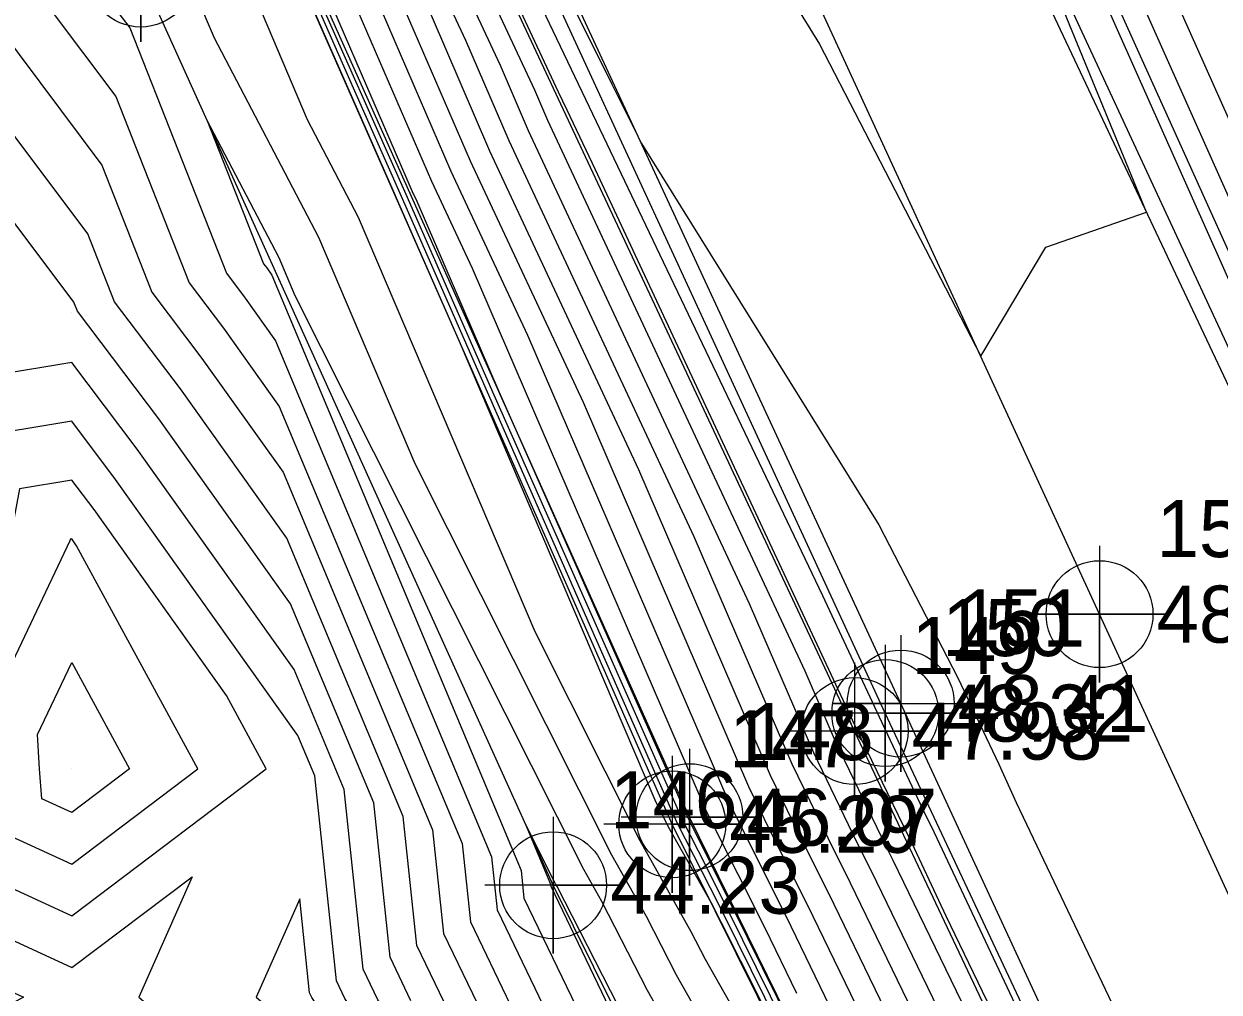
# Model space of a CAD drawing. Extents: x 2090860 to 2091277, y 159470 to 160080.
# Drawn here: x 2091087.9 to 2091140.3, y 159590.2 to 159632.7 of the extents above; entities that cross this region are included whole.
import ezdxf

# ---------------------------------------------------------------- set-up
doc = ezdxf.new("R2010")
doc.units = 0
for name, color, linetype in [('DTM Contours Major', 7, 'Continuous'), ('DTM Contours Minor', 7, 'Continuous'), ('Exist DTM Breakline', 7, 'Continuous'), ('Exist DTM Breakline Cogo Elevation', 7, 'Continuous'), ('Exist DTM Breakline Cogo Number', 7, 'Continuous'), ('Exist DTM Breakline Cogo Point CELL', 7, 'Continuous'), ('Exist DTM Crownline', 7, 'Continuous'), ('Exist DTM Crownline Cogo Elevation', 7, 'Continuous'), ('Exist DTM Crownline Cogo Number', 7, 'Continuous'), ('Exist DTM Crownline Cogo Point CELL', 7, 'Continuous'), ('Exist DTM QL2 LIDAR Elevation Point', 7, 'Continuous'), ('Exist Roads EOP', 7, 'Continuous'), ('Exist Roads EOP Cogo Elevation', 7, 'Continuous'), ('Exist Roads EOP Cogo Number', 7, 'Continuous'), ('Exist Roads EOP Cogo Point CELL', 7, 'Continuous'), ('Exist Roads EOT', 7, 'Continuous'), ('Exist Roads EOT Cogo Elevation', 7, 'Continuous'), ('Exist Roads EOT Cogo Number', 7, 'Continuous'), ('Exist Roads EOT Cogo Point CELL', 7, 'Continuous')]:
    doc.layers.add(name, color=color, linetype=linetype)

msp = doc.modelspace()

# ---------------------------------------------------------------- linework, layer by layer
at = {"layer": 'DTM Contours Major'}
for points in [[(2091079.813, 159694.479), (2091091.479, 159670.351), (2091092.674, 159667.942), (2091092.718, 159667.852), (2091101.365, 159650.434), (2091105.185, 159642.793), (2091106.067, 159640.964), (2091111.338, 159629.685), (2091111.718, 159628.889), (2091112.961, 159626.284), (2091124.433, 159601.716), (2091124.607, 159601.347), (2091126.942, 159596.528), (2091128.343, 159593.558), (2091139.93, 159569.539)], [(2091077.176, 159683.472), (2091085.357, 159667.475), (2091085.495, 159667.182), (2091086.555, 159664.923), (2091087.913, 159662.036), (2091093.577, 159649.962), (2091099.498, 159637.849), (2091099.709, 159637.399), (2091104.938, 159625.32), (2091105.136, 159624.896), (2091108.736, 159616.547), (2091117.028, 159597.858), (2091117.244, 159597.435), (2091119.625, 159592.62), (2091130.861, 159569.9)], [(2091082.79, 159680.214), (2091088.287, 159668.846), (2091088.85, 159667.711), (2091089.525, 159666.328), (2091095.999, 159653.287), (2091102.781, 159639.414), (2091105.76, 159633.037), (2091108.329, 159627.103), (2091114.857, 159613.131), (2091120.634, 159599.73), (2091121.876, 159597.167), (2091123.209, 159594.519), (2091129.912, 159580.676)], [(2091163.429, 159579.673), (2091153.599, 159600.613), (2091150.617, 159606.792), (2091148.169, 159612.011), (2091147.459, 159613.481), (2091138.047, 159634.57), (2091135.191, 159640.875), (2091131.528, 159649.079), (2091130.314, 159651.757), (2091121.742, 159670.624), (2091117.989, 159679.115)], [(2091129.857, 159570.34), (2091117.802, 159591.64), (2091117.171, 159592.866), (2091114.927, 159596.852), (2091110.323, 159606.006), (2091102.573, 159624.179), (2091100.334, 159628.452), (2091096.842, 159636.697), (2091095.262, 159642.075), (2091085.023, 159664.299)], [(2091080.029, 159649.409), (2091088.053, 159636.828), (2091089.011, 159633.367), (2091091.931, 159629.479), (2091095.15, 159621.315), (2091096.661, 159619.317), (2091099.104, 159615.886), (2091107.122, 159596.733), (2091107.485, 159593.301), (2091109.226, 159589.679)], [(2091110.007, 159579.993), (2091110.002, 159580.004), (2091103.432, 159589.881), (2091102.785, 159591.228), (2091101.952, 159599.105), (2091099.755, 159604.353), (2091092.873, 159614.018), (2091090, 159617.816), (2091083.295, 159616.705), (2091082.036, 159610), (2091081.379, 159608.621), (2091081.89, 159600), (2091082.493, 159592.493), (2091087.89, 159590), (2091082.789, 159587.211), (2091083.053, 159580), (2091090, 159570.963), (2091096.054, 159573.946), (2091100, 159579.609), (2091100.406, 159579.594), (2091110, 159579.988), (2091110.007, 159579.993)], [(2091088.689, 159598.689), (2091088.584, 159600), (2091088.495, 159601.505), (2091090, 159604.666), (2091092.536, 159600), (2091090, 159598.084), (2091088.689, 159598.689)]]:
    msp.add_lwpolyline(points, dxfattribs=at)
at = {"layer": 'DTM Contours Minor'}
for points in [[(2091080.51, 159698.642), (2091091.966, 159674.206), (2091093.26, 159671.558), (2091094.64, 159668.709), (2091094.706, 159668.575), (2091095.273, 159667.441), (2091100.175, 159657.278), (2091105.245, 159647.055), (2091107.931, 159641.569), (2091110.32, 159636.766), (2091113.678, 159630.044), (2091114.986, 159627.423), (2091125.393, 159610.705), (2091128.86, 159603.992), (2091130.664, 159600.208), (2091131.424, 159598.524), (2091140.273, 159579.961)], [(2091080.273, 159695.626), (2091092.352, 159670.911), (2091092.91, 159669.758), (2091093.68, 159668.217), (2091100.229, 159655.117), (2091106.917, 159641.251), (2091109.366, 159636.01), (2091112.54, 159629.361), (2091122.928, 159607.603), (2091125.409, 159602.289), (2091127.327, 159598.223), (2091127.819, 159597.207), (2091138.555, 159574.438)], [(2091072.913, 159694.755), (2091083.535, 159676.648), (2091087.489, 159668.47), (2091087.894, 159667.653), (2091088.727, 159665.947), (2091093.416, 159656.501), (2091101.96, 159639.023), (2091104.247, 159634.128), (2091107.481, 159626.657), (2091112.427, 159616.072), (2091119.685, 159599.236), (2091120.595, 159597.359), (2091122.273, 159594.024), (2091127.204, 159583.841)], [(2091070.474, 159693.642), (2091081.681, 159673.757), (2091084.964, 159667.339), (2091085.735, 159665.698), (2091086.157, 159664.799), (2091094.809, 159646.403), (2091098.918, 159637.644), (2091102.338, 159629.862), (2091104.449, 159625.11), (2091112.732, 159606.254), (2091116.546, 159597.659), (2091118.37, 159594.073), (2091119.204, 159592.386), (2091123.926, 159582.838)], [(2091080.558, 159690.913), (2091090.681, 159669.974), (2091091.718, 159667.884), (2091091.92, 159667.471), (2091103.748, 159643.645), (2091105.242, 159640.588), (2091110.299, 159629.767), (2091110.873, 159628.44), (2091122.148, 159604.306), (2091123.481, 159601.214), (2091125.721, 159596.589), (2091126.015, 159596.005), (2091138.036, 159571.181)], [(2091073.926, 159690.732), (2091084.279, 159673.082), (2091086.691, 159668.093), (2091086.938, 159667.595), (2091087.929, 159665.566), (2091090.833, 159659.715), (2091101.14, 159638.632), (2091102.735, 159635.218), (2091106.633, 159626.212), (2091109.996, 159619.013), (2091118.736, 159598.741), (2091119.313, 159597.552), (2091121.338, 159593.528), (2091124.496, 159587.006)], [(2091074.923, 159688.329), (2091081.29, 159675.881), (2091085.023, 159669.516), (2091085.893, 159667.717), (2091085.982, 159667.538), (2091087.13, 159665.185), (2091088.251, 159662.929), (2091100.319, 159638.24), (2091101.222, 159636.308), (2091105.785, 159625.766), (2091107.566, 159621.955), (2091117.788, 159598.247), (2091118.031, 159597.744), (2091120.402, 159593.033), (2091121.788, 159590.171)], [(2091081.302, 159687.347), (2091089.883, 159669.598), (2091090.762, 159667.827), (2091091.122, 159667.09), (2091101.165, 159646.859), (2091104.422, 159640.197), (2091108.786, 159630.857), (2091110.025, 159627.994), (2091119.717, 159607.248), (2091122.532, 159600.719), (2091124.44, 159596.782), (2091125.08, 159595.509), (2091135.328, 159574.346)], [(2091092.675, 159687.628), (2091098.961, 159674.873), (2091100.257, 159672.453), (2091101.069, 159671.14), (2091105.715, 159663.627), (2091115.58, 159644.724), (2091116.703, 159642.969), (2091121.642, 159633.637), (2091122.802, 159631.775), (2091129.869, 159618.089), (2091132.718, 159622.878), (2091137.14, 159624.41), (2091135.353, 159628.744), (2091131.259, 159638.725), (2091131.05, 159639.235), (2091130.694, 159640.103), (2091126.571, 159649.248), (2091126.304, 159649.847), (2091125.204, 159652.293), (2091113.546, 159676.999), (2091113.443, 159677.236), (2091111.307, 159681.76)], [(2091082.046, 159683.781), (2091089.085, 159669.222), (2091089.806, 159667.769), (2091090.323, 159666.709), (2091098.582, 159650.073), (2091103.601, 159639.806), (2091107.273, 159631.947), (2091109.177, 159627.548), (2091117.287, 159610.189), (2091121.583, 159600.225), (2091123.158, 159596.974), (2091124.144, 159595.014), (2091132.62, 159577.511)], [(2091160.862, 159578.349), (2091151.097, 159599.184), (2091148.077, 159605.5), (2091147.174, 159607.39), (2091144.949, 159612.13), (2091141.732, 159619.248), (2091132.693, 159639.533), (2091131.752, 159641.619), (2091127.777, 159650.544), (2091122.382, 159662.543), (2091115.863, 159676.89), (2091115.422, 159677.888), (2091115.345, 159678.061), (2091113.296, 159682.58)], [(2091106.329, 159589.78), (2091105.135, 159592.265), (2091104.537, 159597.919), (2091099.429, 159610.12), (2091094.767, 159616.667), (2091091.883, 159620.481), (2091090.706, 159623.465), (2091084.527, 159631.691), (2091082.5, 159639.015), (2091080.009, 159642.921), (2091074.236, 159645.764), (2091070, 159645.752), (2091065.862, 159650), (2091067.247, 159652.753), (2091070, 159653.131), (2091071.999, 159660.381), (2091071.72, 159660.849), (2091070.48, 159669.697), (2091073.008, 159669.437), (2091070, 159676.646), (2091068.908, 159678.908)], [(2091079.429, 159678.614), (2091085.16, 159667.407), (2091085.615, 159666.44), (2091086.356, 159664.861), (2091091.361, 159654.219), (2091099.113, 159637.695), (2091100.516, 159634.501), (2091104.653, 159625.193), (2091108.518, 159616.394), (2091116.787, 159597.759), (2091117.807, 159595.754), (2091119.414, 159592.503), (2091128.512, 159574.108)], [(2091162.131, 159578.985), (2091150.559, 159603.635), (2091149.359, 159606.123), (2091146.488, 159612.24), (2091146.209, 159612.821), (2091135.187, 159637.514), (2091133.962, 159640.22), (2091129.606, 159649.977), (2091129.069, 159651.161), (2091118.802, 159673.757), (2091116.705, 159678.502)], [(2091132.489, 159565.487), (2091119.34, 159591.568), (2091118.994, 159592.269), (2091118.933, 159592.393), (2091118.041, 159594.145), (2091116.161, 159597.483), (2091115.582, 159598.635), (2091107.01, 159618.735), (2091104.245, 159625.028), (2091104.159, 159625.223), (2091098.723, 159637.593), (2091098.257, 159638.587), (2091085.958, 159664.737)], [(2091127.322, 159571.892), (2091116.525, 159590.966), (2091115.21, 159593.526), (2091113.692, 159596.22), (2091105.065, 159613.377), (2091100.835, 159623.295), (2091096.258, 159632.032), (2091094.714, 159635.676), (2091091.322, 159647.221), (2091083.738, 159663.682)], [(2091080.039, 159652.653), (2091090.83, 159635.734), (2091091.253, 159634.205), (2091092.544, 159632.486), (2091096.783, 159621.732), (2091097.608, 159620.641), (2091098.942, 159618.769), (2091108.415, 159596.14), (2091108.66, 159593.82), (2091110.674, 159589.629)], [(2091104.88, 159589.83), (2091103.96, 159591.747), (2091103.244, 159598.512), (2091099.592, 159607.237), (2091093.82, 159615.342), (2091090.249, 159620.064), (2091090.093, 159620.458), (2091082.284, 159630.854), (2091080, 159639.109), (2091070.926, 159639.074), (2091073.494, 159630), (2091070, 159622.762), (2091067.148, 159620), (2091070, 159615.229), (2091075.044, 159610), (2091070, 159603.341), (2091069.417, 159600.583), (2091067.816, 159600), (2091070, 159597.318), (2091074.705, 159600), (2091080, 159603.65), (2091080.216, 159600), (2091080.944, 159590.944), (2091082.987, 159590)], [(2091086.769, 159632.529), (2091091.319, 159626.472), (2091093.516, 159620.898), (2091095.714, 159617.992), (2091099.267, 159613.003), (2091105.83, 159597.326), (2091106.31, 159592.783), (2091107.777, 159589.73)], [(2091121.017, 159580.102), (2091115.248, 159590.293), (2091113.248, 159594.185), (2091112.457, 159595.589), (2091099.806, 159620.747), (2091099.097, 159622.411), (2091095.932, 159628.452), (2091098.417, 159622.149), (2091098.555, 159621.966), (2091098.779, 159621.652), (2091109.708, 159595.547), (2091109.835, 159594.338), (2091112.122, 159589.579)], [(2091101.984, 159589.931), (2091101.609, 159590.71), (2091100.659, 159599.698), (2091099.917, 159601.47), (2091091.925, 159612.693), (2091090, 159615.239), (2091085.506, 159614.494), (2091084.662, 159610), (2091083.158, 159606.842), (2091083.563, 159600), (2091084.042, 159594.042), (2091090, 159591.29), (2091095.276, 159595.276), (2091092.937, 159590), (2091100, 159583.938), (2091105.788, 159584.212), (2091101.984, 159589.931)], [(2091090.978, 159611.368), (2091090, 159612.662), (2091087.717, 159612.283), (2091087.288, 159610), (2091084.937, 159605.063), (2091085.237, 159600), (2091085.591, 159595.591), (2091090, 159593.555), (2091098.531, 159600), (2091096.782, 159603.218), (2091090.978, 159611.368)], [(2091090.031, 159610.043), (2091090, 159610.085), (2091089.927, 159610.073), (2091089.914, 159610), (2091086.716, 159603.284), (2091086.911, 159600), (2091087.14, 159597.14), (2091090, 159595.819), (2091095.534, 159600), (2091090.215, 159609.785), (2091090.031, 159610.043)], [(2091127.831, 159563.023), (2091114.712, 159588.312), (2091113.972, 159589.62), (2091111.287, 159594.844), (2091111.223, 159594.958), (2091109.886, 159597.615), (2091111, 159594.954), (2091111.011, 159594.856), (2091113.571, 159589.528), (2091113.706, 159589.325), (2091126.097, 159563.682), (2091125.546, 159563.322), (2091126.31, 159562.346), (2091130.432, 159555.15), (2091130.628, 159554.906), (2091130.775, 159554.654), (2091132.153, 159552.145), (2091131.359, 159554.215), (2091130.987, 159555.098), (2091128.247, 159562.039), (2091127.831, 159563.023)], [(2091100.535, 159589.981), (2091100.434, 159590.192), (2091100, 159594.3), (2091098.094, 159590), (2091100, 159588.364), (2091101.562, 159588.438), (2091100.535, 159589.981)]]:
    msp.add_lwpolyline(points, dxfattribs=at)
at = {"layer": 'Exist DTM Breakline'}
for points in [[(2091196.63, 159502.872), (2091177.33, 159544.144), (2091161.139, 159578.46), (2091145.393, 159612.39), (2091128.083, 159650.689), (2091112.842, 159682.377), (2091098.521, 159713.445), (2091088.424, 159738.261), (2091087.489, 159747.73)], [(2091169.184, 159489.682), (2091149.135, 159531.027), (2091132.914, 159565.727), (2091117.093, 159597.885), (2091099.249, 159637.73), (2091085.443, 159667.505), (2091069.301, 159700.059), (2091060.276, 159722.819), (2091058.458, 159734.195), (2091059.361, 159735), (2091060.617, 159735.809)], [(2091168.326, 159489.347), (2091148.612, 159530.829), (2091132.315, 159565.389), (2091116.339, 159597.574), (2091098.698, 159637.587), (2091084.7, 159667.248), (2091067.163, 159699.242), (2091053.414, 159724.442), (2091052.893, 159730.303), (2091057.39, 159734.945)], [(2091175.557, 159492.591), (2091156.216, 159533.598), (2091139.639, 159569.307), (2091124.335, 159601.659), (2091105.938, 159640.92), (2091091.734, 159670.471), (2091076.451, 159703.516), (2091059.361, 159735)], [(2091163.514, 159486.332), (2091143.762, 159527.932), (2091127.118, 159562.647), (2091111.114, 159594.902), (2091093.029, 159634.868), (2091078.886, 159664.385)]]:
    msp.add_lwpolyline(points, dxfattribs=at)
at = {"layer": 'Exist DTM Breakline Cogo Point CELL'}
for points in [[(2091093.029, 159637.868), (2091093.029, 159631.868), (2091093.029, 159634.868), (2091096.029, 159634.868), (2091090.029, 159634.868)], [(2091124.335, 159604.659), (2091124.335, 159598.659), (2091124.335, 159601.659), (2091127.335, 159601.659), (2091121.335, 159601.659)], [(2091117.093, 159600.885), (2091117.093, 159594.885), (2091117.093, 159597.885), (2091120.093, 159597.885), (2091114.093, 159597.885)], [(2091116.339, 159600.574), (2091116.339, 159594.574), (2091116.339, 159597.574), (2091119.339, 159597.574), (2091113.339, 159597.574)], [(2091111.114, 159597.902), (2091111.114, 159591.902), (2091111.114, 159594.902), (2091114.114, 159594.902), (2091108.114, 159594.902)]]:
    msp.add_lwpolyline(points, dxfattribs=at)
for centre in [(2091093.029, 159634.868), (2091124.335, 159601.659), (2091117.093, 159597.885), (2091116.339, 159597.574), (2091111.114, 159594.902)]:
    msp.add_circle(centre, 2.344, dxfattribs=at)
at = {"layer": 'Exist DTM Crownline'}
msp.add_lwpolyline([(2091186.231, 159497.374), (2091150.267, 159573.786), (2091135.077, 159606.786), (2091117.269, 159645.439), (2091102.614, 159676.949), (2091088.105, 159708.377), (2091072.916, 159741.265)], dxfattribs=at)
at = {"layer": 'Exist DTM Crownline Cogo Point CELL'}
msp.add_lwpolyline([(2091135.077, 159609.786), (2091135.077, 159603.786), (2091135.077, 159606.786), (2091138.077, 159606.786), (2091132.077, 159606.786)], dxfattribs=at)
msp.add_circle((2091135.077, 159606.786), 2.344, dxfattribs=at)
at = {"layer": 'Exist DTM QL2 LIDAR Elevation Point'}
for p, q in [((2091090, 159620), (2091090, 159620)), ((2091090, 159610), (2091090, 159610)), ((2091090, 159600), (2091090, 159600)), ((2091100, 159600), (2091100, 159600))]:
    msp.add_line(p, q, dxfattribs=at)
at = {"layer": 'Exist Roads EOP'}
for points in [[(2091195.022, 159502.3), (2091175.816, 159543.301), (2091159.602, 159577.847), (2091143.942, 159611.542), (2091126.198, 159649.797), (2091111.241, 159681.734), (2091096.716, 159712.783), (2091082.116, 159745.373)], [(2091176.987, 159492.996), (2091157.634, 159534.321), (2091140.802, 159570.232), (2091125.679, 159602.447), (2091107.654, 159641.501), (2091093.369, 159671.636), (2091078.486, 159704.356), (2091063.606, 159736.869)]]:
    msp.add_lwpolyline(points, dxfattribs=at)
at = {"layer": 'Exist Roads EOP Cogo Point CELL'}
msp.add_lwpolyline([(2091125.679, 159605.447), (2091125.679, 159599.447), (2091125.679, 159602.447), (2091128.679, 159602.447), (2091122.679, 159602.447)], dxfattribs=at)
msp.add_circle((2091125.679, 159602.447), 2.344, dxfattribs=at)
at = {"layer": 'Exist Roads EOT'}
for points in [[(2091194.37, 159502.018), (2091175.119, 159542.803), (2091158.987, 159577.703), (2091143.368, 159611.224), (2091125.349, 159649.375), (2091110.434, 159681.3), (2091096.012, 159712.514), (2091081.141, 159744.981)], [(2091158.031, 159534.505), (2091141.446, 159570.27), (2091126.357, 159602.867), (2091108.385, 159641.68), (2091094.245, 159672.193), (2091079.271, 159704.671), (2091064.194, 159737.108)]]:
    msp.add_lwpolyline(points, dxfattribs=at)
at = {"layer": 'Exist Roads EOT Cogo Point CELL'}
for points in [[(2091135.077, 159609.786), (2091135.077, 159603.786), (2091135.077, 159606.786), (2091132.077, 159606.786), (2091138.077, 159606.786)], [(2091126.357, 159605.867), (2091126.357, 159599.867), (2091126.357, 159602.867), (2091123.357, 159602.867), (2091129.357, 159602.867)]]:
    msp.add_lwpolyline(points, dxfattribs=at)
for centre in [(2091135.077, 159606.786), (2091126.357, 159602.867)]:
    msp.add_circle(centre, 2.344, dxfattribs=at)

# ---------------------------------------------------------------- texts
at = {"layer": 'Exist DTM Breakline Cogo Elevation'}
for s, p in [('47.98', (2091126.835, 159600.409)), ('46.07', (2091119.593, 159596.635)), ('45.29', (2091118.839, 159596.324)), ('44.23', (2091113.614, 159593.652))]:
    msp.add_text(s, height=2.5, dxfattribs=at).set_placement(p)
at = {"layer": 'Exist DTM Breakline Cogo Number'}
for s, p in [('149', (2091126.835, 159604.159)), ('148', (2091119.593, 159600.385)), ('147', (2091118.839, 159600.074)), ('146', (2091113.614, 159597.402))]:
    msp.add_text(s, height=2.5, dxfattribs=at).set_placement(p)
at = {"layer": 'Exist DTM Crownline Cogo Elevation'}
msp.add_text('48.73', height=2.5, dxfattribs=at).set_placement((2091137.577, 159605.536))
at = {"layer": 'Exist DTM Crownline Cogo Number'}
msp.add_text('153', height=2.5, dxfattribs=at).set_placement((2091137.577, 159609.286))
at = {"layer": 'Exist Roads EOP Cogo Elevation'}
msp.add_text('48.32', height=2.5, dxfattribs=at).set_placement((2091128.179, 159601.197))
at = {"layer": 'Exist Roads EOP Cogo Number'}
msp.add_text('150', height=2.5, dxfattribs=at).set_placement((2091128.179, 159604.947))
at = {"layer": 'Exist Roads EOT Cogo Elevation'}
for s, p in [('48.73', (2091137.577, 159605.536)), ('48.41', (2091128.857, 159601.617))]:
    msp.add_text(s, height=2.5, dxfattribs=at).set_placement(p)
at = {"layer": 'Exist Roads EOT Cogo Number'}
for s, p in [('152', (2091137.577, 159609.286)), ('151', (2091128.857, 159605.367))]:
    msp.add_text(s, height=2.5, dxfattribs=at).set_placement(p)

doc.saveas('drawing.dxf')
